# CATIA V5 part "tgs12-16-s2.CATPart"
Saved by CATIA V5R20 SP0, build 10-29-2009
Part number: TGS12-16-S2
Revision: 1
Definition: design
Nomenclature: TGS12-16-S2
Source: made
Description: NOT SPECIFIED
Bounding box of the stored display mesh (mm): x -22 to 0.8, y 0 to 12, z -5 to 5
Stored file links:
  C:\Users\Raffaele\Desktop\3D X SITO CF\I-MOLD\TGS-S2\tgs12-s2.step\tgs12-16-s2.CATPart
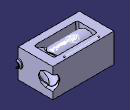
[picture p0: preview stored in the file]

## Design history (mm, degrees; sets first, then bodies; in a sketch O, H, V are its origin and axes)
Set1
  Line1 "LINE #3985": stored without definition
  DatumCurve1 "COMPOSITE_CURVE #4040"
  DatumCurve2 "COMPOSITE_CURVE #4089"
  DatumCurve3 "COMPOSITE_CURVE #4168"
  DatumCurve4 "COMPOSITE_CURVE #4211"
  DatumCurve5 "COMPOSITE_CURVE #4440"
  DatumCurve6 "COMPOSITE_CURVE #4581"
  DatumCurve7 "COMPOSITE_CURVE #4608"
  DatumCurve8 "COMPOSITE_CURVE #4666"
  DatumCurve9 "COMPOSITE_CURVE #4723"
  DatumCurve10 "COMPOSITE_CURVE #4752"
  DatumSurface1 "OPEN_SHELL #3975"
Body1 "MANIFOLD_SOLID_BREP #3976" (main body)
  Solid1: solid without history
